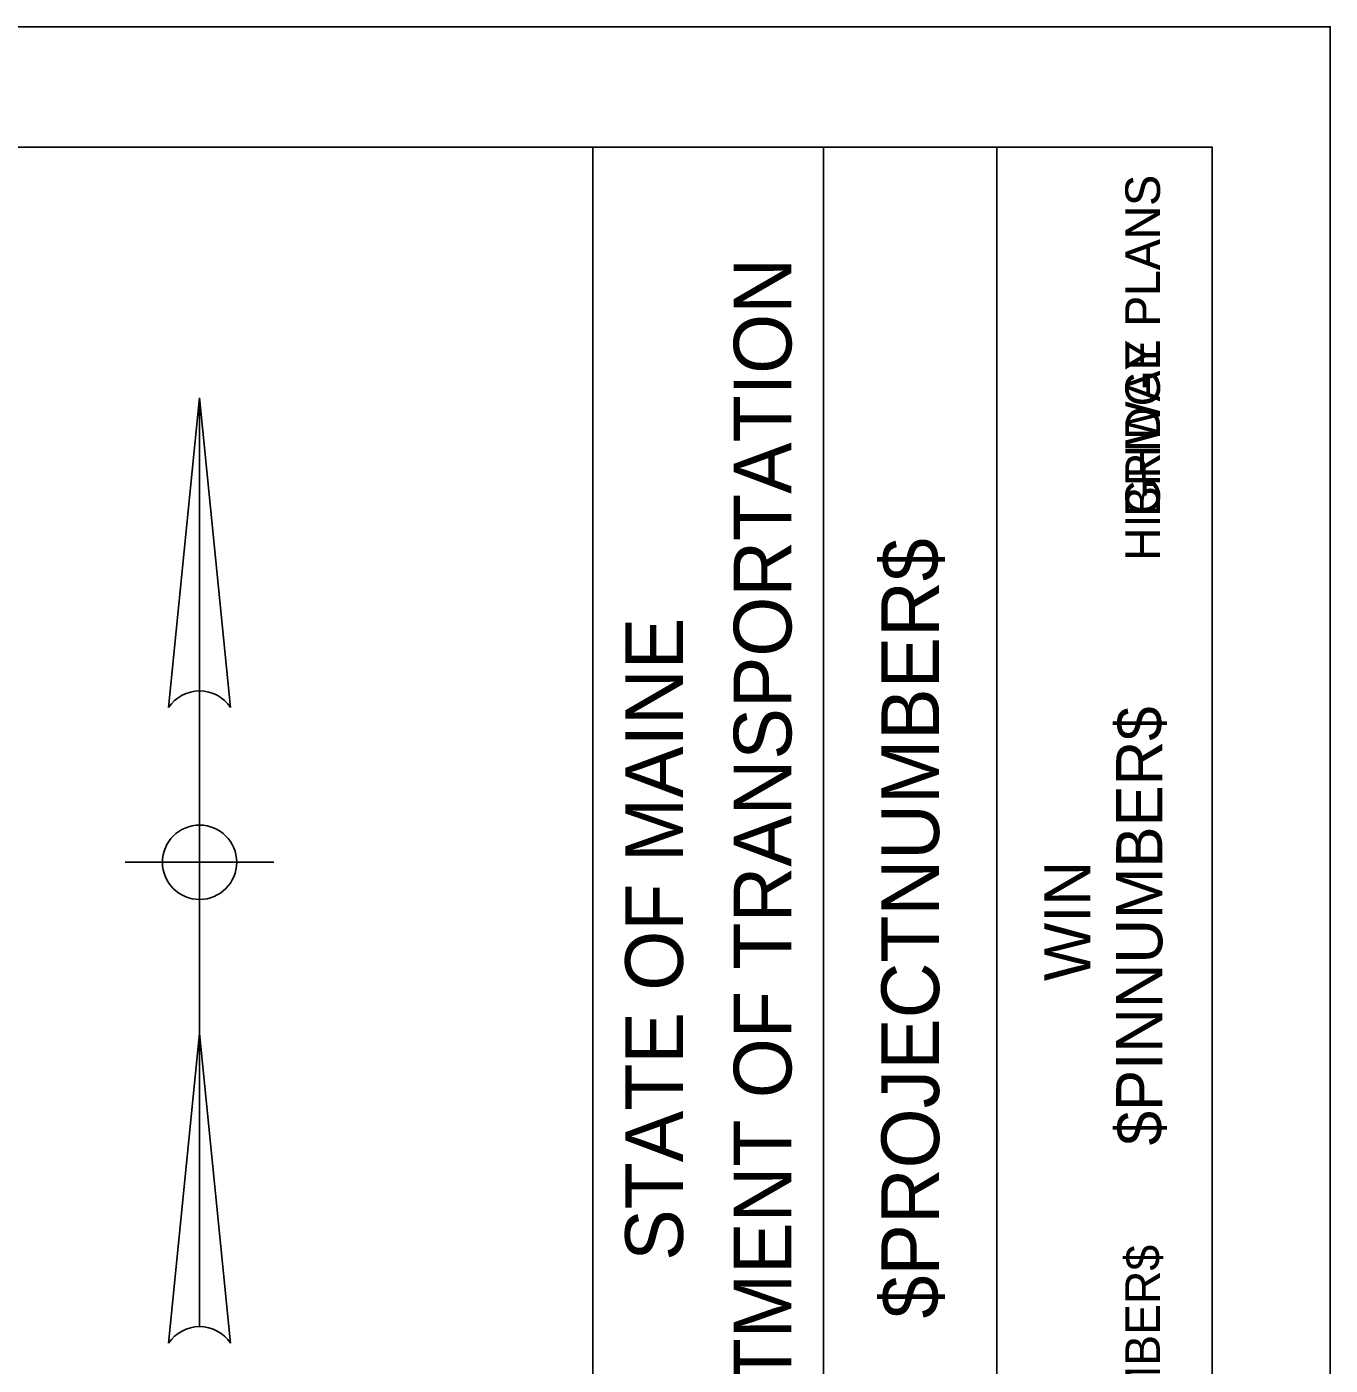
# Model space of a CAD drawing. Extents: x 916887 to 917745, y 329243 to 329793.
# Drawn here: x 917631.9 to 917737.2, y 329684.6 to 329792.7 of the extents above; entities that cross this region are included whole.
import ezdxf

# ---------------------------------------------------------------- set-up
doc = ezdxf.new("R2010")
doc.units = 0
for name, color, linetype in [('Border', 7, 'Continuous'), ('BRIDGE_TITLE', 7, 'Continuous'), ('H_V CONTROLS', 7, 'Continuous'), ('HIGHWAY_TITLE', 7, 'Continuous'), ('PLOT BOUNDARY', 7, 'Continuous')]:
    doc.layers.add(name, color=color, linetype=linetype)

msp = doc.modelspace()

# ---------------------------------------------------------------- linework, layer by layer
at = {"layer": 'Border'}
for p, q in [((917727.63, 329782.99), (916927.63, 329782.99)), ((917677.63, 329258.01), (917677.63, 329783.01)), ((917696.27, 329657.98), (917696.27, 329782.98)), ((917710.25, 329657.98), (917710.25, 329782.98)), ((917727.63, 329258.01), (917727.63, 329783.01))]:
    msp.add_line(p, q, dxfattribs=at)
at = {"layer": 'H_V CONTROLS'}
for p, q in [((917643.39, 329737.73), (917645.89, 329762.73)), ((917645.89, 329762.73), (917645.89, 329687.73)), ((917645.89, 329762.73), (917648.39, 329737.73)), ((917639.89, 329725.23), (917651.89, 329725.23)), ((917643.39, 329686.39), (917645.89, 329711.39)), ((917645.89, 329711.39), (917648.39, 329686.39))]:
    msp.add_line(p, q, dxfattribs=at)
msp.add_circle((917645.89, 329725.23), 3, dxfattribs=at)
for centre in [(917645.89, 329736.07), (917645.89, 329684.73)]:
    msp.add_arc(centre, 3, 33.5573, 146.4427, dxfattribs=at)
at = {"layer": 'PLOT BOUNDARY'}
msp.add_lwpolyline([(916887.17, 329242.7), (917737.16, 329242.7), (917737.16, 329792.7), (916887.17, 329792.7)], close=True, dxfattribs=at)

# ---------------------------------------------------------------- texts
at = {"layer": 'Border'}
for s, height, p in [('DEPARTMENT OF TRANSPORTATION', 4.6588, (917693.67, 329661.53)), ('$PROJECTNUMBER$', 4.6588, (917705.59, 329688.39)), ('STATE OF MAINE', 4.6588, (917684.91, 329693.05)), ('$PINNUMBER$', 3.7264, (917723.61, 329702.37)), ('WIN', 3.726, (917717.81, 329715.64))]:
    msp.add_text(s, height=height, rotation=90, dxfattribs=at).set_placement(p)
at = {"layer": 'BRIDGE_TITLE'}
for s, p in [('BRIDGE PLANS', (917723.42, 329753.12)), ('$BRIDGENUMBER$', (917723.42, 329659.65))]:
    msp.add_text(s, height=2.795, rotation=90, dxfattribs=at).set_placement(p)
at = {"layer": 'HIGHWAY_TITLE'}
msp.add_text('HIGHWAY PLANS', height=2.795, rotation=90, dxfattribs=at).set_placement((917723.42, 329749.57))

doc.saveas('drawing.dxf')
